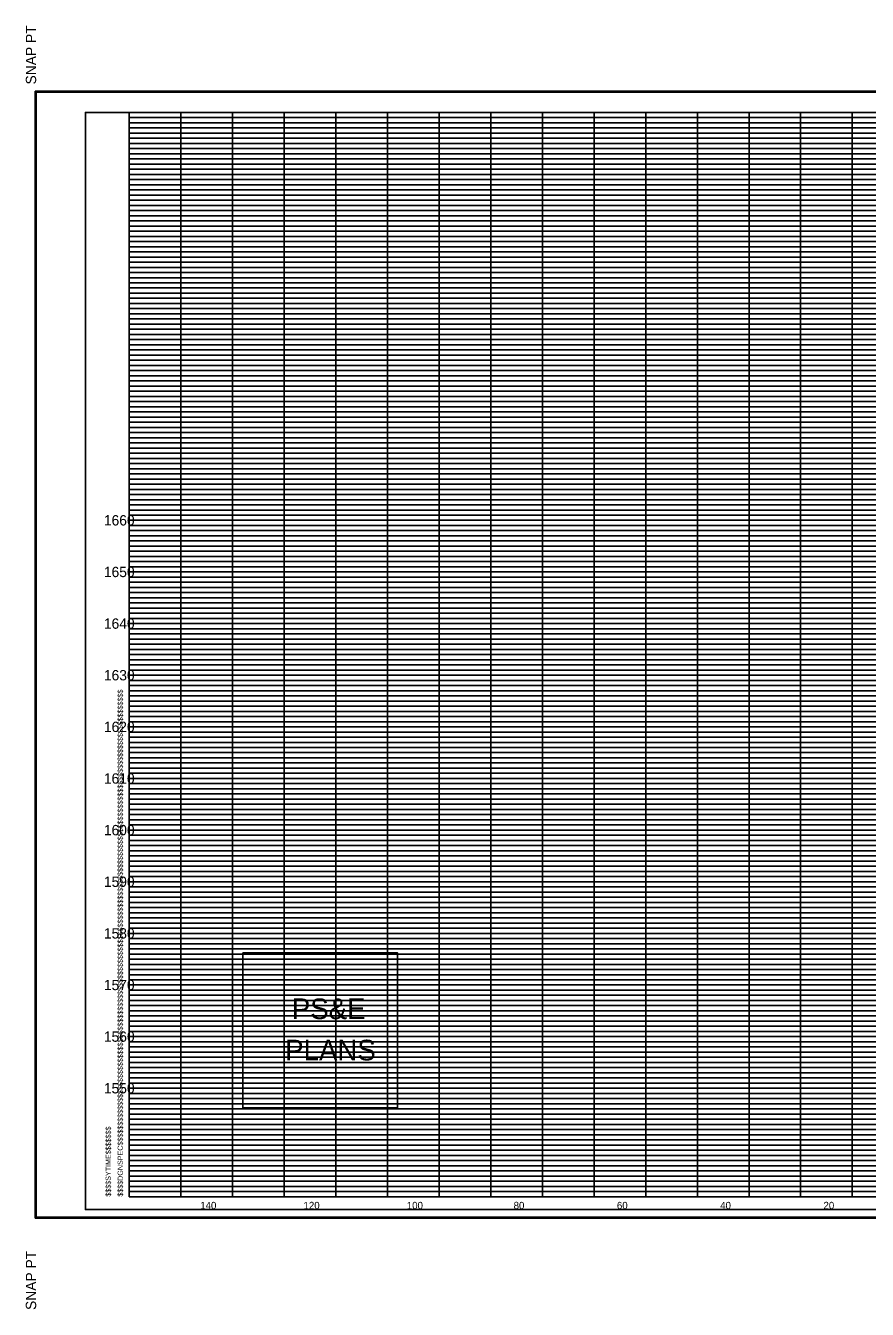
# Model space of a CAD drawing. Extents: x 955 to 1375, y 1248 to 3657.
# Drawn here: x 979.9 to 1142.9, y 3408.2 to 3656.8 of the extents above; entities that cross this region are included whole.
import ezdxf

# ---------------------------------------------------------------- set-up
doc = ezdxf.new("R2010")
doc.units = 0
for name, color, linetype in [('DESIGN - SHEET - Corner Text', 7, 'Continuous'), ('DESIGN - SHEET - Light Grid', 7, 'Continuous'), ('DESIGN - SHEET - Linework', 7, 'Continuous'), ('DESIGN - SHEET - Plot Shape', 7, 'Continuous'), ('DESIGN - TYPICAL - Text', 7, 'Continuous'), ('DESIGN - UTILITIES - Cable (Overhead) with Text', 7, 'Continuous')]:
    doc.layers.add(name, color=color, linetype=linetype)

# ---------------------------------------------------------------- blocks, each defined once
blk = doc.blocks.new('XSTSHT')
at = {"layer": 'DESIGN - SHEET - Light Grid'}
for p, q in [((0, 20.9), (8, 20.9)), ((8, 20.9), (16, 20.9)), ((0, 20.8), (8, 20.8)), ((0, 20.7), (8, 20.7)), ((8, 20.8), (16, 20.8)), ((8, 20.7), (16, 20.7)), ((0, 20.6), (8, 20.6)), ((0, 20.5), (8, 20.5)), ((0, 20.4), (8, 20.4)), ((8, 20.6), (16, 20.6)), ((8, 20.5), (16, 20.5)), ((8, 20.4), (16, 20.4)), ((0, 20.3), (8, 20.3)), ((0, 20.2), (8, 20.2)), ((8, 20.3), (16, 20.3)), ((8, 20.2), (16, 20.2)), ((0, 20.1), (8, 20.1)), ((0, 19.9), (8, 19.9)), ((8, 20.1), (16, 20.1)), ((8, 19.9), (16, 19.9)), ((0, 19.8), (8, 19.8)), ((0, 19.7), (8, 19.7)), ((8, 19.8), (16, 19.8)), ((8, 19.7), (16, 19.7)), ((0, 19.6), (8, 19.6)), ((0, 19.5), (8, 19.5)), ((0, 19.4), (8, 19.4)), ((8, 19.6), (16, 19.6)), ((8, 19.5), (16, 19.5)), ((8, 19.4), (16, 19.4)), ((0, 19.3), (8, 19.3)), ((0, 19.2), (8, 19.2)), ((8, 19.3), (16, 19.3)), ((8, 19.2), (16, 19.2)), ((0, 19.1), (8, 19.1)), ((0, 18.9), (8, 18.9)), ((8, 19.1), (16, 19.1)), ((8, 18.9), (16, 18.9)), ((0, 18.8), (8, 18.8)), ((0, 18.7), (8, 18.7)), ((8, 18.8), (16, 18.8)), ((8, 18.7), (16, 18.7)), ((0, 18.6), (8, 18.6)), ((0, 18.5), (8, 18.5)), ((0, 18.4), (8, 18.4)), ((8, 18.6), (16, 18.6)), ((8, 18.5), (16, 18.5)), ((8, 18.4), (16, 18.4)), ((0, 18.3), (8, 18.3)), ((0, 18.2), (8, 18.2)), ((8, 18.3), (16, 18.3)), ((8, 18.2), (16, 18.2)), ((0, 18.1), (8, 18.1)), ((8, 18.1), (16, 18.1)), ((0, 17.9), (8, 17.9)), ((0, 17.8), (8, 17.8)), ((0, 17.7), (8, 17.7)), ((8, 17.9), (16, 17.9)), ((8, 17.8), (16, 17.8)), ((8, 17.7), (16, 17.7)), ((0, 17.6), (8, 17.6)), ((0, 17.5), (8, 17.5)), ((8, 17.6), (16, 17.6)), ((8, 17.5), (16, 17.5)), ((0, 17.4), (8, 17.4)), ((0, 17.3), (8, 17.3)), ((0, 17.2), (8, 17.2)), ((8, 17.4), (16, 17.4)), ((8, 17.3), (16, 17.3)), ((8, 17.2), (16, 17.2)), ((0, 17.1), (8, 17.1)), ((8, 17.1), (16, 17.1)), ((0, 16.9), (8, 16.9)), ((0, 16.8), (8, 16.8)), ((0, 16.7), (8, 16.7)), ((8, 16.9), (16, 16.9)), ((8, 16.8), (16, 16.8)), ((8, 16.7), (16, 16.7)), ((0, 16.6), (8, 16.6)), ((0, 16.5), (8, 16.5)), ((8, 16.6), (16, 16.6)), ((8, 16.5), (16, 16.5)), ((0, 16.4), (8, 16.4)), ((0, 16.3), (8, 16.3)), ((0, 16.2), (8, 16.2)), ((8, 16.4), (16, 16.4)), ((8, 16.3), (16, 16.3)), ((8, 16.2), (16, 16.2)), ((0, 16.1), (8, 16.1)), ((8, 16.1), (16, 16.1)), ((0, 15.9), (8, 15.9)), ((0, 15.8), (8, 15.8)), ((0, 15.7), (8, 15.7)), ((8, 15.9), (16, 15.9)), ((8, 15.8), (16, 15.8)), ((8, 15.7), (16, 15.7)), ((0, 15.6), (8, 15.6)), ((0, 15.5), (8, 15.5)), ((8, 15.6), (16, 15.6)), ((8, 15.5), (16, 15.5)), ((0, 15.4), (8, 15.4)), ((0, 15.3), (8, 15.3)), ((0, 15.2), (8, 15.2)), ((8, 15.4), (16, 15.4)), ((8, 15.3), (16, 15.3)), ((8, 15.2), (16, 15.2)), ((0, 15.1), (8, 15.1)), ((8, 15.1), (16, 15.1)), ((0, 14.9), (8, 14.9)), ((0, 14.8), (8, 14.8)), ((0, 14.7), (8, 14.7)), ((8, 14.9), (16, 14.9)), ((8, 14.8), (16, 14.8)), ((8, 14.7), (16, 14.7)), ((0, 14.6), (8, 14.6)), ((0, 14.5), (8, 14.5)), ((8, 14.6), (16, 14.6)), ((8, 14.5), (16, 14.5)), ((0, 14.4), (8, 14.4)), ((0, 14.3), (8, 14.3)), ((0, 14.2), (8, 14.2)), ((8, 14.4), (16, 14.4)), ((8, 14.3), (16, 14.3)), ((8, 14.2), (16, 14.2)), ((0, 14.1), (8, 14.1)), ((8, 14.1), (16, 14.1)), ((0, 13.9), (8, 13.9)), ((0, 13.8), (8, 13.8)), ((0, 13.7), (8, 13.7)), ((8, 13.9), (16, 13.9)), ((8, 13.8), (16, 13.8)), ((8, 13.7), (16, 13.7)), ((0, 13.6), (8, 13.6)), ((0, 13.5), (8, 13.5)), ((8, 13.6), (16, 13.6)), ((8, 13.5), (16, 13.5)), ((0, 13.4), (8, 13.4)), ((0, 13.3), (8, 13.3)), ((0, 13.2), (8, 13.2)), ((8, 13.4), (16, 13.4)), ((8, 13.3), (16, 13.3)), ((8, 13.2), (16, 13.2)), ((0, 13.1), (8, 13.1)), ((8, 13.1), (16, 13.1)), ((0, 12.9), (8, 12.9)), ((0, 12.8), (8, 12.8)), ((0, 12.7), (8, 12.7)), ((8, 12.9), (16, 12.9)), ((8, 12.8), (16, 12.8)), ((8, 12.7), (16, 12.7)), ((0, 12.6), (8, 12.6)), ((0, 12.5), (8, 12.5)), ((8, 12.6), (16, 12.6)), ((8, 12.5), (16, 12.5)), ((0, 12.4), (8, 12.4)), ((0, 12.3), (8, 12.3)), ((0, 12.2), (8, 12.2)), ((8, 12.4), (16, 12.4)), ((8, 12.3), (16, 12.3)), ((8, 12.2), (16, 12.2)), ((0, 12.1), (8, 12.1)), ((8, 12.1), (16, 12.1)), ((0, 11.9), (8, 11.9)), ((0, 11.8), (8, 11.8)), ((0, 11.7), (8, 11.7)), ((8, 11.9), (16, 11.9)), ((8, 11.8), (16, 11.8)), ((8, 11.7), (16, 11.7)), ((0, 11.6), (8, 11.6)), ((0, 11.5), (8, 11.5)), ((8, 11.6), (16, 11.6)), ((8, 11.5), (16, 11.5)), ((0, 11.4), (8, 11.4)), ((0, 11.3), (8, 11.3)), ((0, 11.2), (8, 11.2)), ((8, 11.4), (16, 11.4)), ((8, 11.3), (16, 11.3)), ((8, 11.2), (16, 11.2)), ((0, 11.1), (8, 11.1)), ((8, 11.1), (16, 11.1)), ((0, 10.9), (8, 10.9)), ((0, 10.8), (8, 10.8)), ((0, 10.7), (8, 10.7)), ((8, 10.9), (16, 10.9)), ((8, 10.8), (16, 10.8)), ((8, 10.7), (16, 10.7)), ((0, 10.6), (8, 10.6)), ((0, 10.5), (8, 10.5)), ((8, 10.6), (16, 10.6)), ((8, 10.5), (16, 10.5)), ((0, 10.4), (8, 10.4)), ((0, 10.3), (8, 10.3)), ((0, 10.2), (8, 10.2)), ((8, 10.4), (16, 10.4)), ((8, 10.3), (16, 10.3)), ((8, 10.2), (16, 10.2)), ((0, 10.1), (8, 10.1)), ((8, 10.1), (16, 10.1)), ((0, 9.9), (8, 9.9)), ((0, 9.8), (8, 9.8)), ((0, 9.7), (8, 9.7)), ((8, 9.9), (16, 9.9)), ((8, 9.8), (16, 9.8)), ((8, 9.7), (16, 9.7)), ((0, 9.6), (8, 9.6)), ((0, 9.5), (8, 9.5)), ((8, 9.6), (16, 9.6)), ((8, 9.5), (16, 9.5)), ((0, 9.4), (8, 9.4)), ((0, 9.3), (8, 9.3)), ((0, 9.2), (8, 9.2)), ((8, 9.4), (16, 9.4)), ((8, 9.3), (16, 9.3)), ((8, 9.2), (16, 9.2)), ((0, 9.1), (8, 9.1)), ((8, 9.1), (16, 9.1)), ((0, 8.9), (8, 8.9)), ((0, 8.8), (8, 8.8)), ((8, 8.9), (16, 8.9)), ((8, 8.8), (16, 8.8)), ((0, 8.7), (8, 8.7)), ((0, 8.6), (8, 8.6)), ((0, 8.5), (8, 8.5)), ((8, 8.7), (16, 8.7)), ((8, 8.6), (16, 8.6)), ((8, 8.5), (16, 8.5)), ((0, 8.4), (8, 8.4)), ((0, 8.3), (8, 8.3)), ((8, 8.4), (16, 8.4)), ((8, 8.3), (16, 8.3)), ((0, 8.2), (8, 8.2)), ((0, 8.1), (8, 8.1)), ((8, 8.2), (16, 8.2)), ((8, 8.1), (16, 8.1)), ((0, 7.9), (8, 7.9)), ((0, 7.8), (8, 7.8)), ((8, 7.9), (16, 7.9)), ((8, 7.8), (16, 7.8)), ((0, 7.7), (8, 7.7)), ((0, 7.6), (8, 7.6)), ((0, 7.5), (8, 7.5)), ((8, 7.7), (16, 7.7)), ((8, 7.6), (16, 7.6)), ((8, 7.5), (16, 7.5)), ((0, 7.4), (8, 7.4)), ((0, 7.3), (8, 7.3)), ((8, 7.4), (16, 7.4)), ((8, 7.3), (16, 7.3)), ((0, 7.2), (8, 7.2)), ((0, 7.1), (8, 7.1)), ((8, 7.2), (16, 7.2)), ((8, 7.1), (16, 7.1)), ((0, 6.9), (8, 6.9)), ((0, 6.8), (8, 6.8)), ((8, 6.9), (16, 6.9)), ((8, 6.8), (16, 6.8)), ((0, 6.7), (8, 6.7)), ((0, 6.6), (8, 6.6)), ((0, 6.5), (8, 6.5)), ((8, 6.7), (16, 6.7)), ((8, 6.6), (16, 6.6)), ((8, 6.5), (16, 6.5)), ((0, 6.4), (8, 6.4)), ((0, 6.3), (8, 6.3)), ((8, 6.4), (16, 6.4)), ((8, 6.3), (16, 6.3)), ((0, 6.2), (8, 6.2)), ((0, 6.1), (8, 6.1)), ((8, 6.2), (16, 6.2)), ((8, 6.1), (16, 6.1)), ((0, 5.9), (8, 5.9)), ((0, 5.8), (8, 5.8)), ((8, 5.9), (16, 5.9)), ((8, 5.8), (16, 5.8)), ((0, 5.7), (8, 5.7)), ((0, 5.6), (8, 5.6)), ((0, 5.5), (8, 5.5)), ((8, 5.7), (16, 5.7)), ((8, 5.6), (16, 5.6)), ((8, 5.5), (16, 5.5)), ((0, 5.4), (8, 5.4)), ((0, 5.3), (8, 5.3)), ((8, 5.4), (16, 5.4)), ((8, 5.3), (16, 5.3)), ((0, 5.2), (8, 5.2)), ((0, 5.1), (8, 5.1)), ((8, 5.2), (16, 5.2)), ((8, 5.1), (16, 5.1)), ((0, 4.9), (8, 4.9)), ((0, 4.8), (8, 4.8)), ((8, 4.9), (16, 4.9)), ((8, 4.8), (16, 4.8)), ((0, 4.7), (8, 4.7)), ((0, 4.6), (8, 4.6)), ((0, 4.5), (8, 4.5)), ((8, 4.7), (16, 4.7)), ((8, 4.6), (16, 4.6)), ((8, 4.5), (16, 4.5)), ((0, 4.4), (8, 4.4)), ((0, 4.3), (8, 4.3)), ((8, 4.4), (16, 4.4)), ((8, 4.3), (16, 4.3)), ((0, 4.2), (8, 4.2)), ((0, 4.1), (8, 4.1)), ((8, 4.2), (16, 4.2)), ((8, 4.1), (16, 4.1)), ((0, 3.9), (8, 3.9)), ((0, 3.8), (8, 3.8)), ((8, 3.9), (16, 3.9)), ((8, 3.8), (16, 3.8)), ((0, 3.7), (8, 3.7)), ((0, 3.6), (8, 3.6)), ((0, 3.5), (8, 3.5)), ((8, 3.7), (16, 3.7)), ((8, 3.6), (16, 3.6)), ((8, 3.5), (16, 3.5)), ((0, 3.4), (8, 3.4)), ((0, 3.3), (8, 3.3)), ((8, 3.4), (16, 3.4)), ((8, 3.3), (16, 3.3)), ((0, 3.2), (8, 3.2)), ((0, 3.1), (8, 3.1)), ((8, 3.2), (16, 3.2)), ((8, 3.1), (16, 3.1)), ((0, 2.9), (8, 2.9)), ((0, 2.8), (8, 2.8)), ((8, 2.9), (16, 2.9)), ((8, 2.8), (16, 2.8)), ((0, 2.7), (8, 2.7)), ((0, 2.6), (8, 2.6)), ((0, 2.5), (8, 2.5)), ((8, 2.7), (16, 2.7)), ((8, 2.6), (16, 2.6)), ((8, 2.5), (16, 2.5)), ((0, 2.4), (8, 2.4)), ((0, 2.3), (8, 2.3)), ((8, 2.4), (16, 2.4)), ((8, 2.3), (16, 2.3)), ((0, 2.2), (8, 2.2)), ((0, 2.1), (8, 2.1)), ((8, 2.2), (16, 2.2)), ((8, 2.1), (16, 2.1)), ((0, 1.9), (8, 1.9)), ((0, 1.8), (8, 1.8)), ((8, 1.9), (16, 1.9)), ((8, 1.8), (16, 1.8)), ((0, 1.7), (8, 1.7)), ((0, 1.6), (8, 1.6)), ((0, 1.5), (8, 1.5)), ((8, 1.7), (16, 1.7)), ((8, 1.6), (16, 1.6)), ((8, 1.5), (16, 1.5)), ((0, 1.4), (8, 1.4)), ((0, 1.3), (8, 1.3)), ((8, 1.4), (16, 1.4)), ((8, 1.3), (16, 1.3)), ((0, 1.2), (8, 1.2)), ((0, 1.1), (8, 1.1)), ((8, 1.2), (16, 1.2)), ((8, 1.1), (16, 1.1)), ((0, 0.9), (8, 0.9)), ((0, 0.8), (8, 0.8)), ((8, 0.9), (16, 0.9)), ((8, 0.8), (16, 0.8)), ((0, 0.7), (8, 0.7)), ((0, 0.6), (8, 0.6)), ((0, 0.5), (8, 0.5)), ((8, 0.7), (16, 0.7)), ((8, 0.6), (16, 0.6)), ((8, 0.5), (16, 0.5)), ((0, 0.4), (8, 0.4)), ((0, 0.3), (8, 0.3)), ((8, 0.4), (16, 0.4)), ((8, 0.3), (16, 0.3)), ((0, 0.2), (8, 0.2)), ((0, 0.1), (8, 0.1)), ((8, 0.2), (16, 0.2)), ((8, 0.1), (16, 0.1))]:
    blk.add_line(p, q, dxfattribs=at)
at = {"layer": 'DESIGN - SHEET - Linework'}
for p, q in [((-1.823, -0.414), (-1.823, 21.414)), ((-1.823, 21.414), (32.217, 21.414)), ((1, 0), (1, 21)), ((2, 0), (2, 21)), ((3, 0), (3, 21)), ((4, 0), (4, 21)), ((5, 0), (5, 21)), ((6, 0), (6, 21)), ((7, 0), (7, 21)), ((8, 0), (8, 21)), ((9, 0), (9, 21)), ((10, 0), (10, 21)), ((11, 0), (11, 21)), ((12, 0), (12, 21)), ((13, 0), (13, 21)), ((14, 0), (14, 21)), ((0, 20), (28, 20)), ((0, 19), (32, 19)), ((0, 18), (32, 18)), ((0, 17), (32, 17)), ((0, 16), (32, 16)), ((0, 15), (32, 15)), ((0, 14), (32, 14)), ((0, 13), (32, 13)), ((0, 12), (32, 12)), ((0, 11), (32, 11)), ((0, 10), (32, 10)), ((0, 9), (32, 9)), ((0, 8), (32, 8)), ((0, 7), (32, 7)), ((0, 6), (32, 6)), ((0, 5), (32, 5)), ((0, 4), (32, 4)), ((0, 3), (32, 3)), ((0, 2), (32, 2)), ((0, 1), (32, 1)), ((-1.823, -0.414), (32.217, -0.414))]:
    blk.add_line(p, q, dxfattribs=at)
blk.add_lwpolyline([(0, 21), (0, 0), (32, 0), (32, 21), (0, 21)], dxfattribs=at)
at = {"layer": 'DESIGN - SHEET - Plot Shape'}
for points in [[(-1.803, 21.394), (32.197, 21.394), (32.197, -0.394), (-1.803, -0.394)], [(-0.85, 21), (32, 21), (32, -0.25), (-0.85, -0.25)]]:
    blk.add_lwpolyline(points, close=True, dxfattribs=at)
at = {"layer": 'DESIGN - SHEET - Corner Text'}
for s, height, p in [('  SNAP PT', 0.2, (-1.803, 21.394)), ('$$$$DGNSPEC$$$$$$$$$$$$$$$$$$$$$$$$$$$$$$$$$$$$$$$$$$$$$$$$$$$$$$$$$$$$$$$$$$$$$$$$$$$$$$$$$$$$$$$$$$$$$$$$$$$$$$$$$$$$$$$$$$$', 0.100002, (-0.126, 0)), ('$$$$SYTIME$$$$$$$', 0.1, (-0.358, 0)), ('SNAP PT  ', 0.2, (-1.803, -2.194))]:
    blk.add_text(s, height=height, rotation=90, dxfattribs=at).set_placement(p)

msp = doc.modelspace()

# ---------------------------------------------------------------- linework, layer by layer
at = {"layer": 'DESIGN - SHEET - Corner Text'}
msp.add_lwpolyline([(1021.96, 3477.21), (1021.96, 3447.21), (1051.96, 3447.21), (1051.96, 3477.21)], close=True, dxfattribs=at)
at = {"layer": 'DESIGN - SHEET - Plot Shape'}
msp.add_lwpolyline([(991.5, 3427.5), (1320, 3427.5), (1320, 3640), (991.5, 3640)], close=True, dxfattribs=at)

# ---------------------------------------------------------------- block references
at = {"layer": 'DESIGN - UTILITIES - Cable (Overhead) with Text', "xscale": 10, "yscale": 10}
msp.add_blockref('XSTSHT', (1000, 3430), dxfattribs=at)

# ---------------------------------------------------------------- texts
at = {"layer": 'DESIGN - SHEET - Corner Text'}
for s, p in [('PS&E', (1031.48, 3464.39)), ('PLANS', (1030.19, 3456.39))]:
    msp.add_text(s, height=4, dxfattribs=at).set_placement(p)
at = {"layer": 'DESIGN - TYPICAL - Text'}
for s, height, p in [('     1660     ', 2, (991.37, 3560)), ('     1650     ', 2, (991.37, 3550)), ('     1640     ', 2, (991.37, 3540)), ('     1630     ', 2, (991.37, 3530)), ('     1620     ', 2, (991.37, 3520)), ('     1610     ', 2, (991.37, 3510)), ('     1600     ', 2, (991.37, 3500)), ('     1590     ', 2, (991.37, 3490)), ('     1580     ', 2, (991.37, 3480)), ('     1570     ', 2, (991.37, 3470)), ('     1560     ', 2, (991.37, 3460)), ('     1550     ', 2, (991.37, 3450)), ('     140     ', 1.4, (1011.14, 3427.6)), ('     120     ', 1.4, (1031.14, 3427.6)), ('     100     ', 1.4, (1051.14, 3427.6)), ('     80     ', 1.4, (1071.82, 3427.6)), ('     60     ', 1.4, (1091.82, 3427.6)), ('     40     ', 1.4, (1111.82, 3427.6)), ('     20     ', 1.4, (1131.82, 3427.6))]:
    msp.add_text(s, height=height, dxfattribs=at).set_placement(p)

doc.saveas('drawing.dxf')
